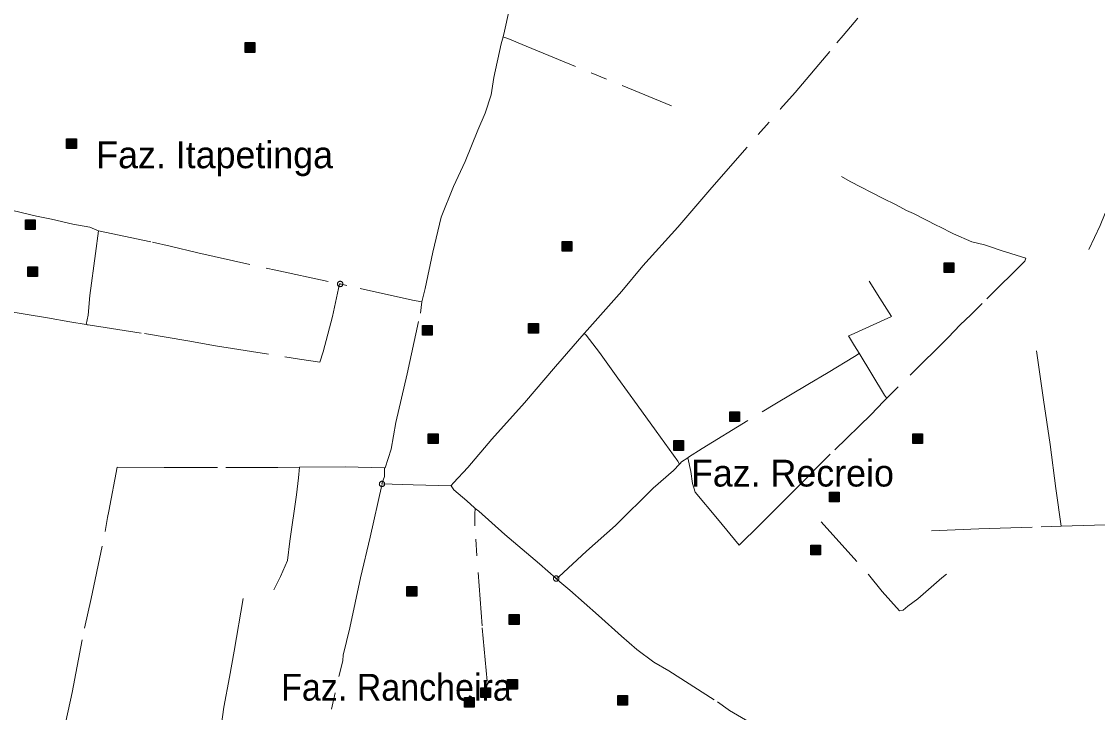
# Model space of a CAD drawing. Extents: x 393.5 to 446.9, y 8064.8 to 8120.4.
# Drawn here: x 412.88 to 419.31, y 8082.08 to 8086.21 of the extents above; entities that cross this region are included whole.
import ezdxf

# ---------------------------------------------------------------- set-up
doc = ezdxf.new("R2010")
doc.units = 0
doc.header["$LTSCALE"] = 0.064
doc.header["$PDMODE"] = 32
doc.header["$PDSIZE"] = 0.032
doc.linetypes.add('DOT_DASHED', pattern=[7.7, 5, -1.2, 0.3, -1.2])
doc.layers.add('2', color=7, linetype='Continuous', lineweight=25)
doc.layers.add('22', color=7, linetype='DOT_DASHED', lineweight=13)
doc.layers.add('61', color=7, linetype='Continuous')

msp = doc.modelspace()

# ---------------------------------------------------------------- hatches: boundary and pattern name
at = {"layer": '2'}
for points in [[(414.2165, 8086.0792), (414.2745, 8086.0792), (414.2745, 8086.0212), (414.2165, 8086.0212)], [(413.149, 8085.5046), (413.207, 8085.5046), (413.207, 8085.4466), (413.149, 8085.4466)], [(412.9035, 8085.0204), (412.9615, 8085.0204), (412.9615, 8084.9624), (412.9035, 8084.9624)], [(416.1104, 8084.8912), (416.1684, 8084.8912), (416.1684, 8084.8332), (416.1104, 8084.8332)], [(418.3926, 8084.765), (418.4506, 8084.765), (418.4506, 8084.707), (418.3926, 8084.707)], [(412.9172, 8084.7394), (412.9752, 8084.7394), (412.9752, 8084.6814), (412.9172, 8084.6814)], [(415.2751, 8084.3899), (415.3331, 8084.3899), (415.3331, 8084.3319), (415.2751, 8084.3319)], [(415.9102, 8084.4021), (415.9682, 8084.4021), (415.9682, 8084.3441), (415.9102, 8084.3441)], [(417.1128, 8083.8736), (417.1708, 8083.8736), (417.1708, 8083.8156), (417.1128, 8083.8156)], [(415.3105, 8083.7424), (415.3685, 8083.7424), (415.3685, 8083.6844), (415.3105, 8083.6844)], [(418.2054, 8083.7422), (418.2634, 8083.7422), (418.2634, 8083.6842), (418.2054, 8083.6842)], [(416.7784, 8083.7018), (416.8364, 8083.7018), (416.8364, 8083.6438), (416.7784, 8083.6438)], [(417.7084, 8083.3947), (417.7664, 8083.3947), (417.7664, 8083.3367), (417.7084, 8083.3367)], [(417.5963, 8083.0769), (417.6543, 8083.0769), (417.6543, 8083.0189), (417.5963, 8083.0189)], [(415.183, 8082.8303), (415.241, 8082.8303), (415.241, 8082.7723), (415.183, 8082.7723)], [(415.7947, 8082.6627), (415.8527, 8082.6627), (415.8527, 8082.6047), (415.7947, 8082.6047)], [(415.7847, 8082.2745), (415.8427, 8082.2745), (415.8427, 8082.2165), (415.7847, 8082.2165)], [(415.6238, 8082.2251), (415.6818, 8082.2251), (415.6818, 8082.1671), (415.6238, 8082.1671)], [(416.4422, 8082.1792), (416.5002, 8082.1792), (416.5002, 8082.1212), (416.4422, 8082.1212)], [(415.5258, 8082.1686), (415.5838, 8082.1686), (415.5838, 8082.1106), (415.5258, 8082.1106)]]:
    msp.add_hatch(color=256, dxfattribs=at).paths.add_polyline_path(points)

# ---------------------------------------------------------------- linework, layer by layer
for points in [[(414.2165, 8086.0792), (414.2745, 8086.0792), (414.2745, 8086.0212), (414.2165, 8086.0212)], [(413.149, 8085.5046), (413.207, 8085.5046), (413.207, 8085.4466), (413.149, 8085.4466)], [(412.9035, 8085.0204), (412.9615, 8085.0204), (412.9615, 8084.9624), (412.9035, 8084.9624)], [(416.1104, 8084.8912), (416.1684, 8084.8912), (416.1684, 8084.8332), (416.1104, 8084.8332)], [(418.3926, 8084.765), (418.4506, 8084.765), (418.4506, 8084.707), (418.3926, 8084.707)], [(412.9172, 8084.7394), (412.9752, 8084.7394), (412.9752, 8084.6814), (412.9172, 8084.6814)], [(415.2751, 8084.3899), (415.3331, 8084.3899), (415.3331, 8084.3319), (415.2751, 8084.3319)], [(415.9102, 8084.4021), (415.9682, 8084.4021), (415.9682, 8084.3441), (415.9102, 8084.3441)], [(417.1128, 8083.8736), (417.1708, 8083.8736), (417.1708, 8083.8156), (417.1128, 8083.8156)], [(415.3105, 8083.7424), (415.3685, 8083.7424), (415.3685, 8083.6844), (415.3105, 8083.6844)], [(418.2054, 8083.7422), (418.2634, 8083.7422), (418.2634, 8083.6842), (418.2054, 8083.6842)], [(416.7784, 8083.7018), (416.8364, 8083.7018), (416.8364, 8083.6438), (416.7784, 8083.6438)], [(417.7084, 8083.3947), (417.7664, 8083.3947), (417.7664, 8083.3367), (417.7084, 8083.3367)], [(417.5963, 8083.0769), (417.6543, 8083.0769), (417.6543, 8083.0189), (417.5963, 8083.0189)], [(415.183, 8082.8303), (415.241, 8082.8303), (415.241, 8082.7723), (415.183, 8082.7723)], [(415.7947, 8082.6627), (415.8527, 8082.6627), (415.8527, 8082.6047), (415.7947, 8082.6047)], [(415.7847, 8082.2745), (415.8427, 8082.2745), (415.8427, 8082.2165), (415.7847, 8082.2165)], [(415.6238, 8082.2251), (415.6818, 8082.2251), (415.6818, 8082.1671), (415.6238, 8082.1671)], [(416.4422, 8082.1792), (416.5002, 8082.1792), (416.5002, 8082.1212), (416.4422, 8082.1212)], [(415.5258, 8082.1686), (415.5838, 8082.1686), (415.5838, 8082.1106), (415.5258, 8082.1106)]]:
    msp.add_lwpolyline(points, close=True, dxfattribs=at)
at = {"layer": '22'}
for p, q in [((415.7586, 8086.1136), (415.7615, 8086.1126)), ((414.7838, 8084.6376), (414.7794, 8084.6386)), ((413.2663, 8084.3953), (413.2718, 8084.3944)), ((416.8624, 8083.6), (416.8664, 8083.6026)), ((415.052, 8083.539), (415.0496, 8083.5391)), ((416.812, 8083.562), (416.8148, 8083.5652)), ((415.4463, 8083.431), (415.4478, 8083.4349)), ((416.0746, 8082.8782), (416.0761, 8082.8769))]:
    msp.add_line(p, q, dxfattribs=at)
for points in [[(415.8501, 8086.5197), (415.7926, 8086.2646), (415.7668, 8086.1479), (415.7586, 8086.1136)], [(416.2424, 8084.3421), (416.2595, 8084.3618), (416.4661, 8084.5948), (416.5934, 8084.7467), (416.8024, 8084.977), (417.0045, 8085.2141), (417.4162, 8085.684), (417.5028, 8085.7824), (417.7527, 8086.0777), (417.7896, 8086.1215), (417.8775, 8086.226)], [(415.7586, 8086.1136), (415.7462, 8086.0713), (415.7011, 8085.8701), (415.6864, 8085.767), (415.6504, 8085.6575), (415.607, 8085.556), (415.5301, 8085.3695), (415.4605, 8085.2206), (415.3868, 8085.0358), (415.3379, 8084.8278), (415.2921, 8084.6103), (415.2708, 8084.5306)], [(415.7615, 8086.1126), (415.7865, 8086.1038), (415.8945, 8086.058), (416.7788, 8085.6958)], [(411.483, 8085.3002), (411.6774, 8085.2983), (411.8567, 8085.2917), (411.9811, 8085.2705), (412.1088, 8085.2394), (412.2889, 8085.1969), (412.6588, 8085.1152), (412.8274, 8085.076), (412.9682, 8085.0433), (413.0582, 8085.0253), (413.1859, 8084.9958), (413.2881, 8084.9763), (413.3392, 8084.9554)], [(417.7794, 8085.2801), (417.831, 8085.2498), (418.0255, 8085.1496), (418.1075, 8085.1101), (418.1683, 8085.0767), (418.2108, 8085.0585), (418.3542, 8084.9851)], [(419.259, 8084.8433), (419.3253, 8084.9877), (419.3556, 8085.0599), (419.5605, 8085.1152), (419.8001, 8085.1762), (419.9205, 8085.206), (419.9333, 8085.2087), (419.9348, 8085.209)], [(413.2663, 8084.3953), (413.1683, 8084.4119), (413.0341, 8084.4348), (412.7803, 8084.4773), (412.5724, 8084.5052), (412.4497, 8084.5248), (412.4448, 8084.5379), (412.4488, 8084.5918), (412.4815, 8084.8046), (412.5066, 8084.9419), (412.5168, 8085.0611)], [(413.3392, 8084.9554), (413.3224, 8084.8193), (413.2875, 8084.5694), (413.2781, 8084.4513), (413.2663, 8084.3953)], [(413.3392, 8084.9554), (413.6619, 8084.887), (413.767, 8084.8626), (413.9323, 8084.8233), (414.3997, 8084.7202), (414.7794, 8084.6386)], [(418.3542, 8084.9851), (418.3627, 8084.981), (418.4493, 8084.9369), (418.5581, 8084.8887), (418.634, 8084.872), (418.6711, 8084.8588)], [(418.6711, 8084.8588), (418.7334, 8084.8368), (418.8823, 8084.7912), (418.8762, 8084.7745), (418.6201, 8084.5214), (418.5522, 8084.4532)], [(413.2718, 8084.3944), (413.2774, 8084.3935), (413.6147, 8084.3412), (413.8734, 8084.2987), (414.0387, 8084.2676), (414.5412, 8084.1892), (414.6624, 8084.1712), (414.682, 8084.2317), (414.7377, 8084.4444), (414.7794, 8084.6386)], [(415.2708, 8084.5306), (415.2151, 8084.5404), (414.8236, 8084.6288), (414.7838, 8084.6376)], [(417.8855, 8084.2235), (417.8581, 8084.2675), (417.8217, 8084.3282), (417.8369, 8084.3343), (418.078, 8084.4427), (418.0097, 8084.5536), (417.9459, 8084.6537)], [(415.052, 8083.539), (415.0881, 8083.6504), (415.1159, 8083.8107), (415.1839, 8084.1003), (415.2632, 8084.4633), (415.2708, 8084.5306)], [(418.5522, 8084.4532), (418.4894, 8084.393), (418.4165, 8084.3186), (418.0517, 8083.9557)], [(415.4478, 8083.4349), (415.4608, 8083.4505), (415.546, 8083.541), (415.6908, 8083.7106), (415.8845, 8083.9281), (416.0711, 8084.1443), (416.2418, 8084.3414)], [(416.2418, 8084.3414), (416.2423, 8084.342), (416.2424, 8084.3421)], [(416.812, 8083.562), (416.8016, 8083.5799), (416.672, 8083.7582), (416.5594, 8083.9153), (416.4425, 8084.0745), (416.3342, 8084.2294), (416.2537, 8084.3328), (416.2444, 8084.3395), (416.2418, 8084.3414)], [(419.0924, 8083.191), (419.0616, 8083.4165), (419.0273, 8083.6787), (418.9875, 8083.9456), (418.945, 8084.2382)], [(416.8664, 8083.6026), (416.9473, 8083.6551), (417.3818, 8083.9205), (417.5778, 8084.0374), (417.6993, 8084.1087), (417.8581, 8084.2052), (417.8852, 8084.2233), (417.8855, 8084.2235)], [(417.8855, 8084.2235), (418.0359, 8083.9745), (418.0493, 8083.9586), (418.0517, 8083.9557)], [(416.8624, 8083.6), (416.8798, 8083.5179), (416.8889, 8083.4451), (416.9056, 8083.3934), (417.0378, 8083.2341), (417.1684, 8083.0771), (417.2921, 8083.1998), (417.4869, 8083.3938), (417.7391, 8083.6465), (417.9562, 8083.8588), (418.0313, 8083.935), (418.0517, 8083.9557)], [(416.8148, 8083.5652), (416.8235, 8083.5748), (416.8624, 8083.6)], [(413.393, 8083.2438), (413.4016, 8083.28), (413.4517, 8083.5439), (413.731, 8083.5412), (414.1011, 8083.5423), (414.4103, 8083.5418), (414.541, 8083.5428)], [(414.3873, 8082.8099), (414.427, 8082.8899), (414.4686, 8082.9857), (414.4831, 8083.1014), (414.5221, 8083.3782), (414.5339, 8083.4794), (414.541, 8083.5428)], [(415.0496, 8083.5391), (414.8131, 8083.5452), (414.5411, 8083.5428), (414.541, 8083.5428)], [(415.0337, 8083.4432), (415.0494, 8083.4884), (415.0496, 8083.5391)], [(416.812, 8083.562), (416.7767, 8083.5227), (416.6551, 8083.4173), (416.4286, 8083.1958), (416.2566, 8083.0419), (416.091, 8082.8878), (416.0761, 8082.8769)], [(414.8022, 8082.4211), (414.8417, 8082.583), (414.9045, 8082.8823), (414.9632, 8083.1244), (415.0334, 8083.442), (415.0337, 8083.4432)], [(415.0337, 8083.4432), (415.2209, 8083.4376), (415.4463, 8083.431)], [(415.4463, 8083.431), (415.4626, 8083.408), (415.54, 8083.3415), (415.5873, 8083.2998), (415.5909, 8083.2967)], [(415.6617, 8082.2659), (415.6323, 8082.5957), (415.588, 8083.1924), (415.5887, 8083.2654), (415.5909, 8083.2967)], [(415.5909, 8083.2967), (415.6125, 8083.2805), (415.7687, 8083.1422), (415.9743, 8082.9651), (416.0746, 8082.8782)], [(413.0453, 8081.5475), (413.093, 8081.7739), (413.1449, 8082.0238), (413.1829, 8082.197), (413.2552, 8082.5826), (413.2952, 8082.7586), (413.3795, 8083.1593), (413.393, 8083.2438)], [(417.6587, 8083.2177), (417.9404, 8082.9028), (418.0231, 8082.8005), (418.1255, 8082.6844), (418.1492, 8082.6903), (418.1772, 8082.713)], [(419.0924, 8083.191), (419.2919, 8083.1963), (419.5317, 8083.2045), (419.7253, 8083.2123)], [(418.318, 8083.1625), (418.5997, 8083.1753), (418.9739, 8083.1878), (419.0924, 8083.191)], [(418.1772, 8082.713), (418.2358, 8082.7579), (418.3793, 8082.8816), (418.4072, 8082.9046)], [(416.0761, 8082.8769), (416.0965, 8082.8593), (416.1562, 8082.8091), (416.3274, 8082.6569), (416.4646, 8082.5338), (416.5569, 8082.4538), (416.6587, 8082.3792), (416.7482, 8082.3263), (417.0381, 8082.1419), (417.1024, 8082.096)], [(413.9911, 8081.6012), (414.0242, 8081.7069), (414.0474, 8081.8219), (414.0892, 8082.1093), (414.1217, 8082.2892), (414.1495, 8082.4445), (414.2153, 8082.8203)], [(414.6415, 8081.6873), (414.7848, 8082.3314), (414.8, 8082.3884), (414.8022, 8082.4211)], [(417.1024, 8082.096), (417.1115, 8082.0903), (417.2534, 8082.0055), (417.3606, 8081.9336), (417.4665, 8081.8712), (417.5696, 8081.8021), (417.6511, 8081.7519)]]:
    msp.add_lwpolyline(points, dxfattribs=at)
for p in [(414.7838, 8084.6376), (415.0337, 8083.4432), (416.0746, 8082.8782)]:
    msp.add_point(p, dxfattribs=at)

# ---------------------------------------------------------------- texts
at = {"layer": '61'}
for s, p in [('Faz. Itapetinga', (413.3258, 8085.3292)), ('Faz. Recreio', (416.8802, 8083.4278))]:
    msp.add_text(s, height=0.16, dxfattribs=at).set_placement(p)
at = {"layer": '61', "width": 0.95}
msp.add_text('Faz. Rancheira', height=0.16, dxfattribs=at).set_placement((414.4309, 8082.1489))

doc.saveas('drawing.dxf')
